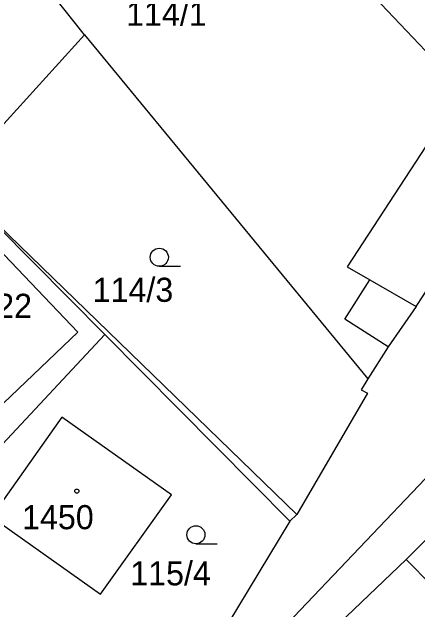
# Model space of a CAD drawing. Extents: x -555757 to -553364, y -1100723 to -1096439.
# Drawn here: x -554339.16 to -554305.53, y -1100614.32 to -1100564.79 of the extents above; entities that cross this region are included whole.
import ezdxf

# ---------------------------------------------------------------- set-up
doc = ezdxf.new("R2010")
doc.units = 0
for name, color, linetype in [('BUDOVY', 7, 'Continuous'), ('C$SLO$PARCELY', 7, 'Continuous'), ('HRANICE$PARCELY', 7, 'Continuous'), ('SLOUPY', 7, 'Continuous'), ('SLUCKOV$$C$RA', 7, 'Continuous'), ('ZNA$KY$KULTUR', 7, 'Continuous')]:
    doc.layers.add(name, color=color, linetype=linetype)

# ---------------------------------------------------------------- blocks, each defined once
blk = doc.blocks.new('4$02')
at = {"layer": 'SLOUPY'}
blk.add_circle((0, 0), 0.175, dxfattribs=at)
blk = doc.blocks.new('3$04')
at = {"layer": 'ZNA$KY$KULTUR'}
blk.add_line((0.007, 0), (1.757, 0), dxfattribs=at)
blk.add_circle((0.007, 0.75), 0.75, dxfattribs=at)

msp = doc.modelspace()

# ---------------------------------------------------------------- linework, layer by layer
at = {"layer": 'HRANICE$PARCELY'}
for p, q in [((-554333.45, -1100537.74), (-554301.75, -1100571.27)), ((-554333.13, -1100566.69), (-554347.96, -1100548.09)), ((-554344.12, -1100578.77), (-554333.13, -1100566.69)), ((-554333.13, -1100566.69), (-554309.62, -1100595.23)), ((-554344.12, -1100578.77), (-554331.44, -1100591.55)), ((-554309.45, -1100587.01), (-554305.59, -1100589.22)), ((-554351.77, -1100613.23), (-554331.44, -1100591.55)), ((-554331.44, -1100591.55), (-554316.1, -1100607.02)), ((-554320.15, -1100619.56), (-554298.66, -1100597)), ((-554316.1, -1100607.02), (-554322.31, -1100617.32))]:
    msp.add_line(p, q, dxfattribs=at)
for points in [[(-554305.59, -1100589.22), (-554305.03, -1100588.34), (-554302.17, -1100583.87), (-554296.15, -1100574.49), (-554290.74, -1100566.04)], [(-554301.75, -1100571.27), (-554311.33, -1100585.93), (-554309.45, -1100587.01)], [(-554339.85, -1100597.25), (-554333.7, -1100591.35), (-554342.08, -1100582.59), (-554346.05, -1100586.33), (-554340.48, -1100592.18), (-554342.58, -1100594.3), (-554339.85, -1100597.25)], [(-554305.59, -1100589.22), (-554307.93, -1100592.56), (-554309.62, -1100595.23)], [(-554309.62, -1100595.23), (-554310.17, -1100596.13), (-554309.65, -1100596.41), (-554315.52, -1100606.47), (-554316.1, -1100607.02)], [(-554335.02, -1100598.4), (-554340.87, -1100606.66), (-554331.8, -1100613.09), (-554325.92, -1100604.85), (-554335.02, -1100598.4)]]:
    msp.add_lwpolyline(points, dxfattribs=at)
at = {"layer": 'SLUCKOV$$C$RA'}
for p, q in [((-554315.52, -1100606.47), (-554344.12, -1100578.77)), ((-554311.52, -1100590.29), (-554309.45, -1100587.01)), ((-554307.93, -1100592.56), (-554311.52, -1100590.29)), ((-554306.42, -1100610.2), (-554304.62, -1100608.42)), ((-554315.13, -1100618.5), (-554306.42, -1100610.2)), ((-554306.42, -1100610.2), (-554302.91, -1100613.83))]:
    msp.add_line(p, q, dxfattribs=at)

# ---------------------------------------------------------------- block references
at = {"layer": 'BUDOVY'}
msp.add_blockref('4$02', (-554333.77, -1100604.54), dxfattribs=at)
at = {"layer": 'ZNA$KY$KULTUR'}
for p in [(-554326.93, -1100585.89), (-554323.89, -1100608.91)]:
    msp.add_blockref('3$04', p, dxfattribs=at)

# ---------------------------------------------------------------- texts
at = {"layer": 'C$SLO$PARCELY'}
for s, p in [('114/1', (-554329.679, -1100565.94)), ('114/3', (-554332.457, -1100588.84)), ('2322', (-554343.439, -1100590.17)), ('1450', (-554338.318, -1100607.7)), ('115/4', (-554329.337, -1100612.36))]:
    msp.add_text(s, height=2, dxfattribs=at).set_placement(p)

doc.saveas('drawing.dxf')
